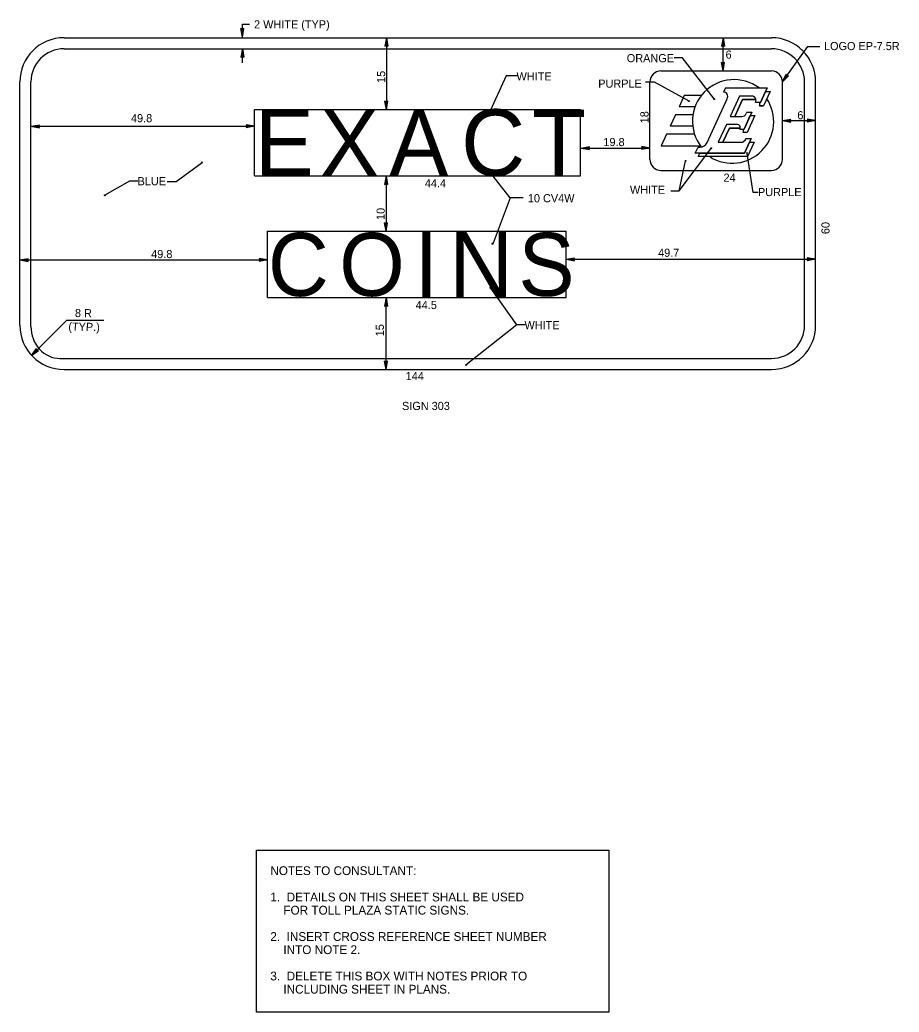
# Model space of a CAD drawing. Extents: x 60712 to 61344, y 9358 to 10016.
# Drawn here: x 61041.4 to 61343.7, y 9675.2 to 10016.1 of the extents above; entities that cross this region are included whole.
import ezdxf

# ---------------------------------------------------------------- set-up
doc = ezdxf.new("R2010")
doc.units = 0
for name, color, linetype in [('1', 7, 'Continuous'), ('2', 7, 'Continuous'), ('3', 7, 'Continuous'), ('52', 7, 'Continuous'), ('TextAlert', 7, 'Continuous')]:
    doc.layers.add(name, color=color, linetype=linetype)

msp = doc.modelspace()

# ---------------------------------------------------------------- linework, layer by layer
at = {"layer": '1'}
for p, q in [((61117.92, 10010.14), (61117.92, 10014.6)), ((61117.92, 10014.6), (61120.42, 10014.6)), ((61167.47, 10009.96), (61167.47, 9985.26)), ((61283.19, 9998.56), (61283.19, 10009.96)), ((61303.61, 9994.75), (61312.37, 10006.97)), ((61312.37, 10006.97), (61316.5, 10006.97)), ((61117.92, 10001.27), (61117.92, 10006.22)), ((61266.41, 10003.1), (61268.96, 10003.1)), ((61268.96, 10003.1), (61280.03, 9988.96)), ((61208.64, 9996.87), (61202.53, 9983.6)), ((61212.53, 9996.87), (61208.64, 9996.87)), ((61256.5, 9994.82), (61259.51, 9994.82)), ((61259.51, 9994.82), (61271.36, 9988.25)), ((61045.24, 9979.52), (61122.14, 9979.52)), ((61303.61, 9981.48), (61315.01, 9981.48)), ((61268.06, 9957.39), (61278.98, 9971.82)), ((61293.58, 9956.81), (61291.42, 9970.14)), ((61095.15, 9960.55), (61104.05, 9967.1)), ((61268.06, 9957.39), (61270.31, 9967.66)), ((61167.32, 9962.46), (61167.32, 9943.46)), ((61209.97, 9954.9), (61202.45, 9964.58)), ((61079.11, 9960.67), (61070.65, 9955.83)), ((61081.97, 9960.67), (61079.11, 9960.67)), ((61092.08, 9960.55), (61095.15, 9960.55)), ((61265.21, 9957.39), (61268.06, 9957.39)), ((61295.28, 9956.81), (61293.58, 9956.81)), ((61209.97, 9954.9), (61204.09, 9939.33)), ((61214.49, 9954.9), (61209.97, 9954.9)), ((61041.41, 9933.61), (61126.61, 9933.61)), ((61229.18, 9933.81), (61315.01, 9933.81)), ((61212.31, 9911.25), (61203.37, 9923.92)), ((61045.41, 9900.74), (61057.55, 9912.89)), ((61057.55, 9912.89), (61070.26, 9912.94)), ((61212.31, 9911.25), (61194.82, 9897.53)), ((61215.11, 9911.25), (61212.31, 9911.25))]:
    msp.add_line(p, q, dxfattribs=at)
for centre, major_axis, ratio in [((61271.43, 9988.19), (0, 0.157), 0.906668), ((61280.14, 9988.85), (0, 0.157), 0.906668), ((61202.4, 9983.34), (0.194, 0), 0.980296), ((61279.09, 9971.96), (0, 0.157), 0.906668), ((61291.4, 9970.31), (0, 0.157), 0.906668), ((61104.05, 9967.1), (0, 0.157), 0.906668), ((61270.31, 9967.66), (0, 0.157), 0.906668), ((61202.31, 9964.67), (0.194, 0), 0.980296), ((61070.65, 9955.82), (0, 0.157), 0.906668), ((61203.91, 9939.17), (0.196, 0), 0.97059), ((61203.3, 9924.03), (0.196, 0), 0.97059), ((61194.82, 9897.53), (0, 0.157), 0.906668)]:
    msp.add_ellipse(centre, major_axis=major_axis, ratio=ratio, dxfattribs=at)
at = {"layer": '2'}
for p, q in [((61056.61, 10009.96), (61299.81, 10009.96)), ((61056.61, 10006.16), (61299.81, 10006.16)), ((61261.81, 9998.56), (61299.81, 9998.56)), ((61041.41, 9911.16), (61041.41, 9994.76)), ((61045.21, 9910.76), (61045.21, 9994.76)), ((61258.01, 9968.16), (61258.01, 9994.76)), ((61283.96, 9992.68), (61283.31, 9991.28)), ((61283.96, 9992.68), (61298.34, 9992.68)), ((61298.34, 9992.68), (61296.04, 9987.69)), ((61303.61, 9968.16), (61303.61, 9994.76)), ((61311.21, 9911.16), (61311.21, 9994.76)), ((61315.01, 9911.16), (61315.01, 9994.76)), ((61269.86, 9990.12), (61268.04, 9986.19)), ((61275.72, 9990.12), (61269.86, 9990.12)), ((61288.83, 9989.88), (61285.6, 9982.88)), ((61293.15, 9989.88), (61288.83, 9989.88)), ((61299.4, 9991.5), (61297.09, 9986.51)), ((61297.8, 9991.5), (61299.4, 9991.5)), ((61273.52, 9986.19), (61268.04, 9986.19)), ((61277.7, 9973.99), (61284.62, 9988.99)), ((61289.89, 9988.7), (61287.2, 9982.88)), ((61294.47, 9988.7), (61289.89, 9988.7)), ((61296.04, 9987.69), (61294.34, 9987.69)), ((61295.7, 9986.51), (61297.09, 9986.51)), ((61122.14, 9985.26), (61234.17, 9985.26)), ((61122.14, 9962.46), (61122.14, 9985.26)), ((61234.17, 9962.46), (61234.17, 9985.26)), ((61266.77, 9983.45), (61264.95, 9979.52)), ((61272.81, 9983.45), (61266.77, 9983.45)), ((61285.6, 9982.88), (61289.65, 9982.88)), ((61293.07, 9984.39), (61290.39, 9978.57)), ((61291.38, 9984.39), (61291.16, 9983.9)), ((61291.38, 9984.39), (61293.07, 9984.39)), ((61294.13, 9983.21), (61291.44, 9977.39)), ((61292.53, 9983.21), (61294.13, 9983.21)), ((61272.75, 9979.52), (61264.95, 9979.52)), ((61284.31, 9980.08), (61281.5, 9974.02)), ((61288.21, 9980.08), (61284.31, 9980.08)), ((61263.68, 9976.76), (61261.87, 9972.84)), ((61273.37, 9976.76), (61263.68, 9976.76)), ((61285.36, 9978.9), (61283.1, 9974.02)), ((61289.08, 9978.9), (61285.36, 9978.9)), ((61288.96, 9978.57), (61290.39, 9978.57)), ((61291.44, 9977.39), (61290.05, 9977.39)), ((61261.87, 9972.84), (61275.38, 9972.84)), ((61273.61, 9970.28), (61274.57, 9972.36)), ((61274.57, 9972.36), (61275.28, 9972.36)), ((61281.5, 9974.02), (61289.27, 9974.02)), ((61292.84, 9975.27), (61290.53, 9970.28)), ((61291.15, 9975.27), (61292.84, 9975.27)), ((61293.89, 9974.09), (61291.59, 9969.1)), ((61292.29, 9974.09), (61293.89, 9974.09)), ((61234.38, 9972.05), (61258.01, 9972.05)), ((61290.53, 9970.28), (61273.61, 9970.28)), ((61274.67, 9969.1), (61275.21, 9970.28)), ((61291.59, 9969.1), (61274.67, 9969.1)), ((61122.14, 9962.46), (61234.17, 9962.46)), ((61261.81, 9964.36), (61299.81, 9964.36)), ((61126.61, 9943.46), (61229.18, 9943.46)), ((61126.61, 9920.66), (61126.61, 9943.46)), ((61229.18, 9920.66), (61229.18, 9943.46)), ((61126.61, 9920.66), (61229.18, 9920.66)), ((61167.32, 9895.96), (61167.32, 9920.66)), ((61055.18, 9899.76), (61299.81, 9899.76)), ((61056.61, 9895.96), (61299.81, 9895.96))]:
    msp.add_line(p, q, dxfattribs=at)
for centre, radius, start, end in [((61056.61, 9994.75), 15.2, 90, 180), ((61299.81, 9994.75), 15.2, 0, 90), ((61056.61, 9994.75), 11.4, 90, 180), ((61299.81, 9994.75), 11.4, 0, 90), ((61261.81, 9994.75), 3.8, 90, 180), ((61299.81, 9994.75), 3.8, 0, 90), ((61286.95, 9981.25), 14.31, 52.9547, 218.1763), ((61286.28, 9981.14), 14.31, 238.1578, 33.3171), ((61261.81, 9968.15), 3.8, 180, 270), ((61299.81, 9968.15), 3.8, 270, 360), ((61056.61, 9911.15), 15.2, 180, 270), ((61299.81, 9911.15), 11.4, 270, 0), ((61299.81, 9911.15), 15.2, 270, 0)]:
    msp.add_arc(centre, radius, start, end, dxfattribs=at)
for centre, major_axis, start_param, end_param in [((61283.35, 9989.71), (0, 1.57), 4.241328, 6.314398), ((61293.14, 9988.39), (0, 1.49), 4.227342, 6.283185), ((61294.5, 9987.21), (0, 1.49), 4.227342, 5.041732), ((61289.65, 9984.75), (0, 1.87), 3.141593, 4.241405), ((61288.21, 9979.1), (0, 0.982), 4.144801, 6.283185), ((61288.85, 9978.09), (0, 1.49), 4.227342, 5.041732), ((61275.28, 9975.35), (0, 2.99), 3.141593, 4.241135), ((61289.27, 9976.35), (0, 2.33), 3.141593, 4.232591), ((61055.18, 9910.76), (0, 11), 1.570796, 3.141593)]:
    msp.add_ellipse(centre, major_axis=major_axis, ratio=0.906668, start_param=start_param, end_param=end_param, dxfattribs=at)
at = {"layer": '3'}
for p, q in [((61288.83, 9989.88), (61285.6, 9982.88)), ((61293.15, 9989.88), (61288.83, 9989.88)), ((61296.04, 9987.69), (61297.8, 9991.5)), ((61299.4, 9991.5), (61297.09, 9986.51)), ((61297.8, 9991.5), (61299.4, 9991.5)), ((61287.2, 9982.88), (61289.89, 9988.7)), ((61289.89, 9988.7), (61294.47, 9988.7)), ((61297.09, 9986.51), (61295.7, 9986.51)), ((61295.78, 9987.69), (61296.04, 9987.69)), ((61285.6, 9982.88), (61287.2, 9982.88)), ((61290.39, 9978.57), (61292.53, 9983.21)), ((61294.13, 9983.21), (61291.44, 9977.39)), ((61292.53, 9983.21), (61294.13, 9983.21)), ((61284.31, 9980.08), (61281.5, 9974.02)), ((61288.21, 9980.08), (61284.31, 9980.08)), ((61283.1, 9974.02), (61285.36, 9978.9)), ((61285.36, 9978.9), (61289.08, 9978.9)), ((61291.44, 9977.39), (61290.05, 9977.39)), ((61290.13, 9978.57), (61290.39, 9978.57)), ((61281.5, 9974.02), (61281.5, 9974.02)), ((61281.5, 9974.02), (61283.1, 9974.02)), ((61290.53, 9970.28), (61292.29, 9974.09)), ((61293.89, 9974.09), (61291.59, 9969.1)), ((61292.29, 9974.09), (61293.89, 9974.09)), ((61274.67, 9969.1), (61275.21, 9970.28)), ((61291.59, 9969.1), (61274.67, 9969.1)), ((61275.21, 9970.28), (61290.53, 9970.28))]:
    msp.add_line(p, q, dxfattribs=at)
for centre, major_axis, start_param, end_param in [((61293.14, 9988.39), (0, 1.49), 4.924772, 6.283185), ((61294.5, 9987.21), (0, 1.49), 4.227342, 5.041732), ((61288.21, 9979.1), (0, 0.982), 4.511031, 6.283185), ((61288.85, 9978.09), (0, 1.49), 4.227342, 5.041732)]:
    msp.add_ellipse(centre, major_axis=major_axis, ratio=0.906668, start_param=start_param, end_param=end_param, dxfattribs=at)
at = {"layer": '52'}
for p, q in [((61117.92, 10010.14), (61117.41, 10013.06)), ((61117.92, 10012.83), (61117.41, 10013.06)), ((61117.92, 10010.14), (61117.68, 10012.94)), ((61117.92, 10010.14), (61118.44, 10013.06)), ((61118.44, 10013.06), (61117.92, 10012.83)), ((61117.92, 10010.14), (61118.17, 10012.94)), ((61167.47, 10009.96), (61166.95, 10007.04)), ((61167.47, 10009.96), (61167.22, 10007.16)), ((61167.47, 10009.96), (61167.98, 10007.04)), ((61167.47, 10009.96), (61167.71, 10007.16)), ((61283.19, 10009.96), (61282.67, 10007.04)), ((61283.19, 10009.96), (61282.94, 10007.16)), ((61283.19, 10009.96), (61283.7, 10007.04)), ((61283.19, 10009.96), (61283.43, 10007.16)), ((61166.95, 10007.04), (61167.47, 10007.26)), ((61167.47, 10007.26), (61167.98, 10007.04)), ((61282.67, 10007.04), (61283.19, 10007.26)), ((61283.19, 10007.26), (61283.7, 10007.04)), ((61117.92, 10006.22), (61117.41, 10003.3)), ((61117.41, 10003.3), (61117.92, 10003.53)), ((61117.92, 10006.22), (61117.68, 10003.42)), ((61117.92, 10006.22), (61118.44, 10003.3)), ((61117.92, 10006.22), (61118.17, 10003.42)), ((61117.92, 10003.53), (61118.44, 10003.3)), ((61283.19, 9998.56), (61282.67, 10001.47)), ((61283.19, 10001.25), (61282.67, 10001.47)), ((61283.19, 9998.56), (61282.94, 10001.35)), ((61283.19, 9998.56), (61283.7, 10001.47)), ((61283.7, 10001.47), (61283.19, 10001.25)), ((61283.19, 9998.56), (61283.43, 10001.35)), ((61303.61, 9994.75), (61304.89, 9997.42)), ((61303.61, 9994.75), (61305.04, 9997.17)), ((61303.61, 9994.75), (61305.44, 9996.89)), ((61303.61, 9994.75), (61305.73, 9996.82)), ((61305.18, 9996.94), (61304.89, 9997.42)), ((61305.73, 9996.82), (61305.18, 9996.94)), ((61167.47, 9985.26), (61166.95, 9988.17)), ((61167.47, 9987.95), (61166.95, 9988.17)), ((61167.47, 9985.26), (61167.22, 9988.05)), ((61167.47, 9985.26), (61167.98, 9988.17)), ((61167.98, 9988.17), (61167.47, 9987.95)), ((61167.47, 9985.26), (61167.71, 9988.05)), ((61045.24, 9979.52), (61048.15, 9980.04)), ((61045.24, 9979.52), (61048.03, 9979.77)), ((61045.24, 9979.52), (61048.15, 9979.01)), ((61045.24, 9979.52), (61048.03, 9979.28)), ((61047.93, 9979.52), (61048.15, 9980.04)), ((61048.15, 9979.01), (61047.93, 9979.52)), ((61122.14, 9979.52), (61119.23, 9980.04)), ((61119.23, 9980.04), (61119.45, 9979.52)), ((61122.14, 9979.52), (61119.23, 9979.01)), ((61119.45, 9979.52), (61119.23, 9979.01)), ((61122.14, 9979.52), (61119.35, 9979.77)), ((61122.14, 9979.52), (61119.35, 9979.28)), ((61303.61, 9981.48), (61306.52, 9982)), ((61303.61, 9981.48), (61306.41, 9981.73)), ((61303.61, 9981.48), (61306.52, 9980.97)), ((61303.61, 9981.48), (61306.41, 9981.24)), ((61306.3, 9981.48), (61306.52, 9982)), ((61306.52, 9980.97), (61306.3, 9981.48)), ((61315.01, 9981.48), (61312.09, 9980.97)), ((61312.32, 9981.48), (61312.09, 9980.97)), ((61315.01, 9981.48), (61312.1, 9982)), ((61312.1, 9982), (61312.32, 9981.48)), ((61315.01, 9981.48), (61312.21, 9981.73)), ((61315.01, 9981.48), (61312.21, 9981.24)), ((61234.38, 9972.05), (61237.29, 9972.57)), ((61234.38, 9972.05), (61237.17, 9972.3)), ((61237.07, 9972.05), (61237.29, 9972.57)), ((61258.01, 9972.05), (61255.1, 9972.57)), ((61255.1, 9972.57), (61255.32, 9972.05)), ((61258.01, 9972.05), (61255.21, 9972.3)), ((61234.38, 9972.05), (61237.29, 9971.54)), ((61234.38, 9972.05), (61237.17, 9971.81)), ((61237.29, 9971.54), (61237.07, 9972.05)), ((61258.01, 9972.05), (61255.09, 9971.54)), ((61255.32, 9972.05), (61255.09, 9971.54)), ((61258.01, 9972.05), (61255.21, 9971.81)), ((61167.32, 9962.46), (61166.8, 9959.54)), ((61167.32, 9962.46), (61167.07, 9959.66)), ((61167.32, 9962.46), (61167.83, 9959.54)), ((61167.32, 9962.46), (61167.56, 9959.66)), ((61166.8, 9959.54), (61167.32, 9959.76)), ((61167.32, 9959.76), (61167.83, 9959.54)), ((61167.32, 9943.46), (61166.8, 9946.37)), ((61167.32, 9946.15), (61166.8, 9946.37)), ((61167.32, 9943.46), (61167.07, 9946.25)), ((61167.32, 9943.46), (61167.83, 9946.37)), ((61167.83, 9946.37), (61167.32, 9946.15)), ((61167.32, 9943.46), (61167.56, 9946.26)), ((61041.41, 9933.61), (61044.32, 9934.12)), ((61041.41, 9933.61), (61044.21, 9933.85)), ((61041.41, 9933.61), (61044.32, 9933.1)), ((61041.41, 9933.61), (61044.21, 9933.37)), ((61044.1, 9933.61), (61044.32, 9934.12)), ((61044.32, 9933.1), (61044.1, 9933.61)), ((61126.61, 9933.61), (61123.69, 9934.13)), ((61123.69, 9934.13), (61123.91, 9933.61)), ((61126.61, 9933.61), (61123.69, 9933.1)), ((61123.91, 9933.61), (61123.69, 9933.1)), ((61126.61, 9933.61), (61123.81, 9933.85)), ((61126.61, 9933.61), (61123.81, 9933.37)), ((61229.18, 9933.81), (61232.1, 9934.32)), ((61229.18, 9933.81), (61231.98, 9934.05)), ((61229.18, 9933.81), (61232.1, 9933.29)), ((61229.18, 9933.81), (61231.98, 9933.56)), ((61231.87, 9933.81), (61232.1, 9934.32)), ((61232.1, 9933.29), (61231.87, 9933.81)), ((61315.01, 9933.81), (61312.09, 9933.29)), ((61312.32, 9933.81), (61312.09, 9933.29)), ((61315.01, 9933.81), (61312.1, 9934.32)), ((61312.1, 9934.32), (61312.32, 9933.81)), ((61315.01, 9933.81), (61312.21, 9934.05)), ((61315.01, 9933.81), (61312.21, 9933.56)), ((61167.32, 9920.66), (61166.8, 9917.74)), ((61166.8, 9917.74), (61167.32, 9917.97)), ((61167.32, 9920.66), (61167.07, 9917.86)), ((61167.32, 9920.66), (61167.83, 9917.74)), ((61167.32, 9920.66), (61167.56, 9917.86)), ((61167.32, 9917.97), (61167.83, 9917.74)), ((61045.41, 9900.74), (61047.1, 9903.17)), ((61045.41, 9900.74), (61047.21, 9902.89)), ((61045.41, 9900.74), (61047.56, 9902.55)), ((61045.41, 9900.74), (61047.83, 9902.44)), ((61047.31, 9902.64), (61047.1, 9903.17)), ((61047.83, 9902.44), (61047.31, 9902.64)), ((61167.32, 9895.96), (61166.8, 9898.87)), ((61167.32, 9898.65), (61166.8, 9898.87)), ((61167.32, 9895.96), (61167.07, 9898.75)), ((61167.32, 9895.96), (61167.83, 9898.87)), ((61167.83, 9898.87), (61167.32, 9898.65)), ((61167.32, 9895.96), (61167.56, 9898.75))]:
    msp.add_line(p, q, dxfattribs=at)
at = {"layer": 'TextAlert'}
msp.add_lwpolyline([(61122.78, 9730.76), (61243.86, 9730.76), (61243.86, 9675.16), (61122.78, 9675.16)], close=True, dxfattribs=at)

# ---------------------------------------------------------------- texts
at = {"layer": '1'}
for s, p in [('2 WHITE (TYP)', (61121.94, 10013.14)), ('LOGO EP-7.5R', (61317.88, 10005.69)), ('ORANGE', (61250.08, 10001.53)), ('6', (61284.04, 10002.75)), ('WHITE', (61212.17, 9995.26)), ('PURPLE', (61240.27, 9992.78)), ('49.8', (61079.63, 9980.91)), ('6', (61308.71, 9981.92)), ('19.8', (61242.04, 9972.71)), ('BLUE', (61081.89, 9959.24)), ('24', (61283.33, 9960.46)), ('44.4', (61180.65, 9958.54)), ('WHITE', (61251.16, 9956.33)), ('10 CV4W', (61216.07, 9953.4)), ('PURPLE', (61295.17, 9955.53)), ('49.8', (61086.57, 9934.23)), ('49.7', (61260.85, 9934.67)), ('44.5', (61177.5, 9916.72)), ('WHITE', (61214.91, 9909.8)), ('144', (61174.06, 9892.3)), ('SIGN 303', (61172.8, 9882.04))]:
    msp.add_text(s, height=2.8, dxfattribs=at).set_placement(p)
for s, rotation, p in [('15', 90, (61167.02, 9994.42)), ('18', 90, (61257.56, 9980.54)), ('10', 90, (61166.85, 9947.33)), ('60', 90, (61319.79, 9942.47)), ('8 R', 359.0906, (61060.34, 9913.97)), ('(TYP.)', 359.0906, (61058.08, 9909.31)), ('15', 90, (61166.56, 9907.36))]:
    msp.add_text(s, height=2.8, rotation=rotation, dxfattribs=at).set_placement(p)
at = {"layer": '2'}
for s, height, p in [('E', 22.8, (61122.18, 9962.51)), ('X', 22.8, (61144.58, 9962.5)), ('A', 22.8, (61168.4, 9962.44)), ('C', 22.8, (61193.13, 9962.51)), ('T', 22.8, (61217.44, 9962.45)), ('C', 21.66, (61126.7, 9921.22)), ('O', 21.66, (61151.22, 9921.22)), ('I', 22.8, (61176.92, 9920.68)), ('N', 22.8, (61189.02, 9920.66)), ('S', 21.66, (61212.81, 9921.23))]:
    msp.add_text(s, height=height, dxfattribs=at).set_placement(p)
at = {"layer": 'TextAlert'}
for s, p in [('NOTES TO CONSULTANT:', (61127.53, 9722.26)), ('1.  DETAILS ON THIS SHEET SHALL BE USED', (61127.53, 9713.21)), ('    FOR TOLL PLAZA STATIC SIGNS.', (61127.53, 9708.68)), ('2.  INSERT CROSS REFERENCE SHEET NUMBER', (61127.53, 9699.63)), ('    INTO NOTE 2.', (61127.53, 9695.11)), ('3.  DELETE THIS BOX WITH NOTES PRIOR TO', (61127.53, 9686.06)), ('    INCLUDING SHEET IN PLANS.', (61127.53, 9681.53))]:
    msp.add_text(s, height=3.0168, dxfattribs=at).set_placement(p)

doc.saveas('drawing.dxf')
